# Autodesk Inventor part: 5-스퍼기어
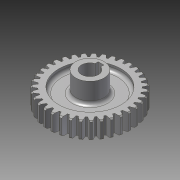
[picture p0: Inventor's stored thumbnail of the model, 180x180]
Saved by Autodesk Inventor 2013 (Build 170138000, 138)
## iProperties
Created: 2013-08
Part Number: 5-스퍼기어
Material: 강
Document SubType Name: Modeling
Designer: 한국산업디자인학원
Categories: <?xml version="1.0" encoding="UTF-16"?> <MemberInstance><Categories><FamilyTemplate><FamilyTemplateParameter ValueType="xs:double" Id="1" ObjectReferenceKey="da
Density: 1 g/cm^3
CustomPartVersion: 1
Author: 한국산업디자인학원
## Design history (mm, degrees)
sketch "Sketch1"
  geometry: C1 r 37 at (0, 0)
  constraints: 1 centre point
  dimensions: "d0" = 74 diameter of C1 (= da_da)
extrude "Extrusion1" new body sketch "Sketch1" distance "d1" = 15 (= da_b); taper "d2" = 0 deg
chamfer "모따기1" distance "d49" = 1; stored, may be unused: second distance "d50" = 2, angle "d51" = 45 deg
workplane "Work Plane2"
feature "피치 지름" dims "d4" = 10, "d5" = 0
workplane "Work Plane8"
workplane "Work Plane9"
feature "스퍼 기어" dims "da_b" = 15, "da_d" = 70, "da_aw" = 70, "da_da" = 74, "da_df" = 65, "da_dw" = 70, angle "da_beta" = 0 deg, "da_lefttooth" = 0, "da_righttooth" = 0
sketch "스케치3"
  geometry: C1 r 27.5 at (0, 0); A1 r 32.5 centre (0, 0) between (9.347, 31.127) and (7.941, 31.515) reference
  constraints: 1 centre point, 1 coincident
  dimensions: "d52" = 55 diameter of C1
extrude "돌출2" cut sketch "스케치3" distance "d54" = 5; taper "d55" = 0 deg
sketch "스케치4"
  geometry: C1 r 27.5 at (0, 0); A1 r 36 centre (0, 0) between (-5.215, 35.62) and (-7.633, 35.181) reference
  constraints: 1 centre point, 1 coincident
  dimensions: "d56" = 55 diameter of C1
extrude "돌출3" cut sketch "스케치4" distance "d58" = 5; taper "d59" = 0 deg
node "작업 평면11"
sketch "스케치5"
  geometry: C1 r 12.5 at (0, 0); 1 further point
  constraints: 1 centre point, 1 coincident
  dimensions: "d61" = 25 diameter of C1
extrude "돌출4" join sketch "스케치5" distance "d63" = 31; taper "d64" = 0 deg
sketch "스케치6"
  geometry: L1 (-2.5, 7.071)-(-2.5, 9.8); L2 (-2.5, 9.8)-(2.5, 9.8); L3 (2.5, 9.8)-(2.5, 7.071); C1 r 12.5 at (0, 0) reference; A1 r 7.5 centre (0, 0) between (-2.5, 7.071) and (2.5, 7.071); 1 further point
  constraints: 6 end point, 2 point on circle, 1 centre point, 1 coincident, 1 midpoint, 1 parallel, 1 perpendicular, 1 vertical, 1 vertical alignment
  dimensions: "d65" = 15 diameter of A1; "d67" = 5 distance between parallel lines of L1 L3; "d68" = 17.3 dimension on A1 L2
extrude "돌출5" cut sketch "스케치6" stored distance "d69" = 31; taper "d70" = 0 deg
fillet "모깎기1" dims "d71" = 3
body "Solid1"
sketch "Sketch2"
  geometry: C1 r 37 at (0, 0) reference; C2 r 35 at (0, 0)
  constraints: 1 centre point, 1 coincident
  dimensions: "d3" = 70 diameter of C2 (= da_dw)
body "Srf1"
other parameters: "d17" = 0, "d34" = 0.8976 (computed from da_z), "d39" = 0, "d41" = 0, "d47" = 0, "d48" = 0, "d60" = 3
